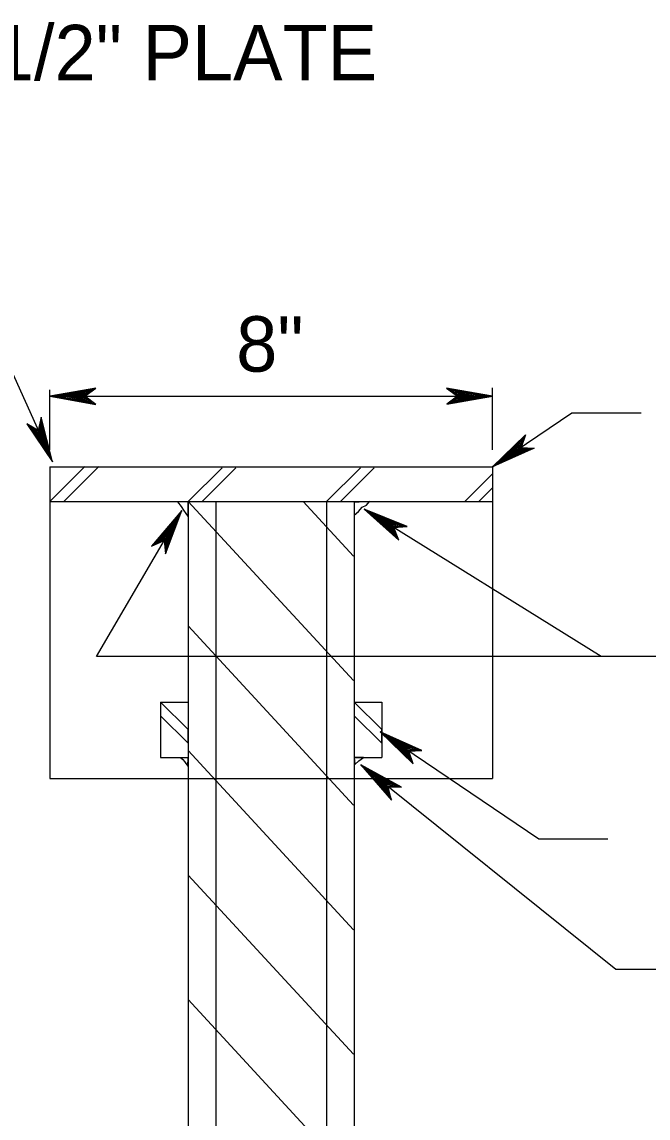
# Model space of a CAD drawing. Extents: x 499883 to 500983, y 499104 to 499764.
# Drawn here: x 500640.4 to 500685.6, y 499221.1 to 499300.2 of the extents above; entities that cross this region are included whole.
import ezdxf

# ---------------------------------------------------------------- set-up
doc = ezdxf.new("R2010")
doc.units = 0
for name, color, linetype in [('1', 7, 'Continuous'), ('24', 7, 'Continuous'), ('5', 7, 'Continuous'), ('60', 7, 'Continuous')]:
    doc.layers.add(name, color=color, linetype=linetype)

msp = doc.modelspace()

# ---------------------------------------------------------------- linework, layer by layer
at = {"layer": '1'}
for p, q in [((500652.382, 499265.584), (500664.324, 499252.644)), ((500660.681, 499265.584), (500664.324, 499261.637)), ((500652.382, 499256.591), (500664.324, 499243.65)), ((500652.382, 499247.597), (500664.324, 499234.657)), ((500652.382, 499238.604), (500664.324, 499225.664)), ((500652.382, 499229.611), (500664.324, 499216.671))]:
    msp.add_line(p, q, dxfattribs=at)
at = {"layer": '24'}
for points in [[(500642.582, 499268.456), (500641.75, 499271.675), (500641.548, 499270.723), (500640.712, 499271.183), (500642.582, 499268.456), (500642.486, 499268.651), (500641.749, 499271.573), (500641.567, 499270.664), (500640.808, 499271.081), (500642.428, 499268.753), (500642.397, 499268.859), (500641.755, 499271.358), (500641.574, 499270.649), (500640.927, 499270.998), (500642.377, 499268.905), (500642.317, 499268.997), (500641.761, 499271.183), (500641.59, 499270.631), (500641.044, 499270.866), (500642.186, 499269.284), (500642.109, 499269.453), (500641.754, 499271), (500641.613, 499270.603), (500641.182, 499270.764), (500642.11, 499269.49), (500642.047, 499269.653), (500641.744, 499270.799), (500641.631, 499270.5), (500641.326, 499270.629), (500641.971, 499269.795), (500641.918, 499269.952), (500641.749, 499270.646), (500641.653, 499270.475), (500641.414, 499270.577), (500641.868, 499270.022), (500641.777, 499270.484), (500641.69, 499270.372), (500641.493, 499270.503), (500641.804, 499270.121), (500641.748, 499270.425), (500641.71, 499270.27), (500641.597, 499270.376), (500641.74, 499270.284), (500641.724, 499270.359)], [(500674.365, 499268.082), (500676.752, 499270.396), (500676.429, 499269.479), (500677.382, 499269.436), (500674.365, 499268.082), (500674.549, 499268.199), (500676.701, 499270.31), (500676.382, 499269.439), (500677.247, 499269.399), (500674.652, 499268.256), (500674.733, 499268.331), (500676.583, 499270.128), (500676.368, 499269.429), (500677.102, 499269.39), (500674.774, 499268.359), (500674.873, 499268.407), (500676.487, 499269.982), (500676.345, 499269.422), (500676.934, 499269.338), (500675.136, 499268.583), (500675.288, 499268.687), (500676.397, 499269.822), (500676.311, 499269.41), (500676.763, 499269.323), (500675.306, 499268.719), (500675.445, 499268.825), (500676.301, 499269.646), (500676.242, 499269.333), (500676.57, 499269.283), (500675.584, 499268.907), (500675.711, 499269.013), (500676.218, 499269.518), (500676.21, 499269.322), (500676.467, 499269.285), (500675.791, 499269.047), (500676.109, 499269.394), (500676.125, 499269.253), (500676.362, 499269.262), (500675.896, 499269.098), (500676.103, 499269.329), (500676.054, 499269.177), (500676.207, 499269.209), (500676.036, 499269.204), (500676.089, 499269.26)], [(500666.244, 499248.957), (500668.631, 499246.643), (500668.308, 499247.561), (500669.261, 499247.603), (500666.244, 499248.957), (500666.428, 499248.84), (500668.579, 499246.73), (500668.261, 499247.601), (500669.126, 499247.64), (500666.53, 499248.783), (500666.611, 499248.709), (500668.462, 499246.911), (500668.247, 499247.61), (500668.981, 499247.65), (500666.653, 499248.68), (500666.752, 499248.633), (500668.366, 499247.057), (500668.224, 499247.617), (500668.813, 499247.701), (500667.014, 499248.456), (500667.167, 499248.352), (500668.276, 499247.217), (500668.189, 499247.629), (500668.641, 499247.716), (500667.185, 499248.32), (500667.324, 499248.214), (500668.18, 499247.393), (500668.121, 499247.707), (500668.448, 499247.756), (500667.463, 499248.132), (500667.59, 499248.026), (500668.096, 499247.522), (500668.089, 499247.717), (500668.345, 499247.755), (500667.67, 499247.992), (500667.988, 499247.645), (500668.003, 499247.786), (500668.241, 499247.777), (500667.775, 499247.941), (500667.981, 499247.71), (500667.933, 499247.863), (500668.085, 499247.831), (500667.915, 499247.835), (500667.968, 499247.779)], [(500664.851, 499246.559), (500667.076, 499244.02), (500666.824, 499244.975), (500667.792, 499244.94), (500664.851, 499246.559), (500665.027, 499246.425), (500667.03, 499244.113), (500666.78, 499245.02), (500667.659, 499244.989), (500665.126, 499246.359), (500665.202, 499246.277), (500666.927, 499244.306), (500666.766, 499245.03), (500667.513, 499245.01), (500665.242, 499246.245), (500665.338, 499246.189), (500666.842, 499244.461), (500666.744, 499245.04), (500667.346, 499245.076), (500665.589, 499245.988), (500665.735, 499245.871), (500666.764, 499244.631), (500666.71, 499245.055), (500667.175, 499245.106), (500665.75, 499245.837), (500665.883, 499245.718), (500666.681, 499244.817), (500666.647, 499245.139), (500666.983, 499245.162), (500666.016, 499245.624), (500666.137, 499245.506), (500666.607, 499244.954), (500666.616, 499245.152), (500666.878, 499245.169), (500666.214, 499245.464), (500666.508, 499245.087), (500666.535, 499245.229), (500666.773, 499245.2), (500666.316, 499245.404), (500666.506, 499245.154), (500666.47, 499245.313), (500666.621, 499245.268), (500666.449, 499245.286), (500666.498, 499245.225)], [(500664.851, 499246.559), (500667.076, 499244.02), (500666.824, 499244.975), (500667.792, 499244.94), (500664.851, 499246.559), (500665.027, 499246.425), (500667.03, 499244.113), (500666.78, 499245.02), (500667.659, 499244.989), (500665.126, 499246.359), (500665.202, 499246.277), (500666.927, 499244.306), (500666.766, 499245.03), (500667.513, 499245.01), (500665.242, 499246.245), (500665.338, 499246.189), (500666.842, 499244.461), (500666.744, 499245.04), (500667.346, 499245.076), (500665.589, 499245.988), (500665.735, 499245.871), (500666.764, 499244.631), (500666.71, 499245.055), (500667.175, 499245.106), (500665.75, 499245.837), (500665.883, 499245.718), (500666.681, 499244.817), (500666.647, 499245.139), (500666.983, 499245.162), (500666.016, 499245.624), (500666.137, 499245.506), (500666.607, 499244.954), (500666.616, 499245.152), (500666.878, 499245.169), (500666.214, 499245.464), (500666.508, 499245.087), (500666.535, 499245.229), (500666.773, 499245.2), (500666.316, 499245.404), (500666.506, 499245.154), (500666.47, 499245.313), (500666.621, 499245.268), (500666.449, 499245.286), (500666.498, 499245.225)]]:
    msp.add_lwpolyline(points, dxfattribs=at)
at = {"layer": '5'}
for p, q in [((500629.104, 499298.008), (500642.582, 499268.456)), ((500674.365, 499269.303), (500674.365, 499273.786)), ((500642.39, 499269.303), (500642.39, 499273.65)), ((500642.39, 499273.183), (500674.365, 499273.183)), ((500642.39, 499265.584), (500644.911, 499268.106)), ((500642.39, 499268.082), (500642.39, 499245.588)), ((500642.39, 499268.082), (500674.365, 499268.082)), ((500643.389, 499265.584), (500645.911, 499268.106)), ((500652.382, 499265.584), (500654.825, 499268.026)), ((500653.381, 499265.584), (500655.814, 499268.016)), ((500662.374, 499265.584), (500664.817, 499268.026)), ((500663.373, 499265.584), (500665.806, 499268.016)), ((500672.367, 499265.584), (500674.339, 499267.556)), ((500674.365, 499268.082), (500674.365, 499245.588)), ((500673.366, 499265.584), (500674.376, 499266.594)), ((500642.39, 499265.584), (500674.365, 499265.584)), ((500652.382, 499265.584), (500652.382, 499170.656)), ((500654.381, 499265.584), (500654.381, 499170.656)), ((500662.374, 499265.499), (500662.374, 499170.656)), ((500664.373, 499265.499), (500664.373, 499170.656)), ((500645.747, 499254.383), (500651.912, 499264.941)), ((500682.22, 499254.383), (500665.083, 499265.035)), ((500682.22, 499254.383), (500645.747, 499254.383)), ((500703.621, 499254.383), (500682.22, 499254.383)), ((500650.383, 499251.095), (500650.383, 499247.098)), ((500650.383, 499251.095), (500652.382, 499251.095)), ((500664.373, 499251.095), (500666.371, 499251.095)), ((500666.371, 499251.095), (500666.371, 499247.098)), ((500650.383, 499247.098), (500652.382, 499247.098)), ((500664.373, 499247.098), (500666.371, 499247.098)), ((500683.275, 499231.776), (500664.851, 499246.559)), ((500642.39, 499245.588), (500652.382, 499245.588)), ((500652.382, 499245.588), (500664.373, 499245.588)), ((500664.373, 499245.588), (500674.365, 499245.588)), ((500708.293, 499231.776), (500683.275, 499231.776))]:
    msp.add_line(p, q, dxfattribs=at)
for points in [[(500642.39, 499273.183), (500645.714, 499272.595), (500644.92, 499273.183), (500645.696, 499273.761), (500642.39, 499273.183), (500642.611, 499273.189), (500645.62, 499272.639), (500644.857, 499273.19), (500645.562, 499273.715), (500642.729, 499273.199), (500642.84, 499273.183), (500645.419, 499272.725), (500644.84, 499273.189), (500645.435, 499273.641), (500642.891, 499273.183), (500643.001, 499273.199), (500645.255, 499272.793), (500644.817, 499273.183), (500645.264, 499273.588), (500643.322, 499273.2), (500643.51, 499273.199), (500645.088, 499272.876), (500644.781, 499273.173), (500645.112, 499273.504), (500643.543, 499273.183), (500643.721, 499273.173), (500644.907, 499272.969), (500644.68, 499273.2), (500644.927, 499273.427), (500643.884, 499273.183), (500644.052, 499273.166), (500644.764, 499273.03), (500644.646, 499273.19), (500644.841, 499273.368), (500644.138, 499273.183), (500644.603, 499273.072), (500644.536, 499273.199), (500644.74, 499273.327), (500644.255, 499273.2), (500644.56, 499273.124), (500644.432, 499273.224), (500644.579, 499273.284), (500644.433, 499273.19), (500644.509, 499273.173)], [(500674.365, 499273.183), (500671.042, 499273.77), (500671.835, 499273.183), (500671.058, 499272.604), (500674.365, 499273.183), (500674.144, 499273.177), (500671.135, 499273.727), (500671.897, 499273.176), (500671.193, 499272.65), (500674.025, 499273.166), (500673.914, 499273.183), (500671.336, 499273.641), (500671.915, 499273.176), (500671.32, 499272.725), (500673.864, 499273.183), (500673.754, 499273.166), (500671.499, 499273.573), (500671.938, 499273.183), (500671.491, 499272.778), (500673.433, 499273.166), (500673.245, 499273.166), (500671.667, 499273.49), (500671.974, 499273.192), (500671.643, 499272.862), (500673.212, 499273.183), (500673.034, 499273.193), (500671.848, 499273.396), (500672.076, 499273.166), (500671.829, 499272.938), (500672.871, 499273.183), (500672.704, 499273.2), (500671.991, 499273.336), (500672.109, 499273.176), (500671.914, 499272.998), (500672.617, 499273.183), (500672.152, 499273.293), (500672.219, 499273.166), (500672.015, 499273.039), (500672.5, 499273.166), (500672.195, 499273.242), (500672.323, 499273.142), (500672.176, 499273.082), (500672.322, 499273.176), (500672.245, 499273.192)], [(500685.095, 499271.962), (500680.099, 499271.962), (500674.365, 499268.082)], [(500651.912, 499264.941), (500649.729, 499262.367), (500650.637, 499262.756), (500650.745, 499261.794), (500651.912, 499264.941), (500651.806, 499264.747), (500649.813, 499262.425), (500650.674, 499262.806), (500650.773, 499261.933), (500651.755, 499264.639), (500651.685, 499264.552), (500649.989, 499262.556), (500650.683, 499262.821), (500650.772, 499262.08), (500651.659, 499264.508), (500651.618, 499264.404), (500650.13, 499262.663), (500650.688, 499262.845), (500650.813, 499262.254), (500651.456, 499264.127), (500651.362, 499263.965), (500650.287, 499262.766), (500650.698, 499262.88), (500650.817, 499262.429), (500651.33, 499263.945), (500651.232, 499263.797), (500650.458, 499262.874), (500650.772, 499262.955), (500650.844, 499262.627), (500651.159, 499263.65), (500651.06, 499263.514), (500650.583, 499262.968), (500650.781, 499262.988), (500650.836, 499262.731), (500651.03, 499263.431), (500650.701, 499263.085), (500650.844, 499263.079), (500650.851, 499262.839), (500650.986, 499263.321), (500650.766, 499263.097), (500650.918, 499263.156), (500650.895, 499263), (500650.888, 499263.173), (500650.835, 499263.115)], [(500665.083, 499265.035), (500667.596, 499262.781), (500667.232, 499263.699), (500668.197, 499263.78), (500665.083, 499265.035), (500665.274, 499264.924), (500667.54, 499262.868), (500667.183, 499263.738), (500668.059, 499263.813), (500665.381, 499264.87), (500665.466, 499264.797), (500667.414, 499263.047), (500667.168, 499263.748), (500667.912, 499263.816), (500665.509, 499264.77), (500665.611, 499264.726), (500667.311, 499263.191), (500667.145, 499263.754), (500667.739, 499263.862), (500665.885, 499264.557), (500666.044, 499264.458), (500667.213, 499263.35), (500667.109, 499263.765), (500667.564, 499263.871), (500666.063, 499264.426), (500666.208, 499264.324), (500667.109, 499263.524), (500667.037, 499263.841), (500667.367, 499263.903), (500666.352, 499264.246), (500666.486, 499264.144), (500667.019, 499263.652), (500667.004, 499263.85), (500667.263, 499263.898), (500666.568, 499264.112), (500666.905, 499263.773), (500666.915, 499263.916), (500667.155, 499263.917), (500666.677, 499264.065), (500666.895, 499263.839), (500666.84, 499263.992), (500666.996, 499263.965), (500666.822, 499263.962), (500666.879, 499263.908)], [(500682.707, 499241.197), (500677.71, 499241.197), (500666.244, 499248.957)]]:
    msp.add_lwpolyline(points, dxfattribs=at)
at = {"layer": '60'}
for points in [[(500652.382, 499265.584), (500651.615, 499265.549), (500651.869, 499265.21), (500652.038, 499264.957), (500652.377, 499264.477)], [(500664.373, 499265.499), (500664.375, 499264.589), (500664.686, 499264.872), (500664.94, 499265.183), (500665.25, 499265.323), (500665.476, 499265.577)], [(500650.383, 499251.095), (500650.383, 499250.096), (500652.37, 499248.122), (500652.37, 499249.121)], [(500664.373, 499251.095), (500664.373, 499250.096), (500666.36, 499248.122), (500666.36, 499249.121)], [(500652.382, 499247.098), (500651.855, 499247.079), (500651.982, 499246.952), (500652.109, 499246.811), (500652.166, 499246.726), (500652.349, 499246.472)], [(500664.373, 499247.098), (500664.418, 499246.578), (500664.7, 499246.86), (500665.053, 499247.1)]]:
    msp.add_lwpolyline(points, close=True, dxfattribs=at)

# ---------------------------------------------------------------- texts
at = {"layer": '5'}
for s, p in [('1/2" PLATE', (500638.26, 499296.008)), ('8"', (500655.843, 499274.962))]:
    msp.add_text(s, height=4, dxfattribs=at).set_placement(p)

doc.saveas('drawing.dxf')
